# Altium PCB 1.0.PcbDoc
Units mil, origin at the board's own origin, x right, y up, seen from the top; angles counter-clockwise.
Board outline 1562.91 x 1190.73 mil, 2 copper layers (Top Layer, Bottom Layer); 62 components, 61 nets, 284 pads, 89 vias.
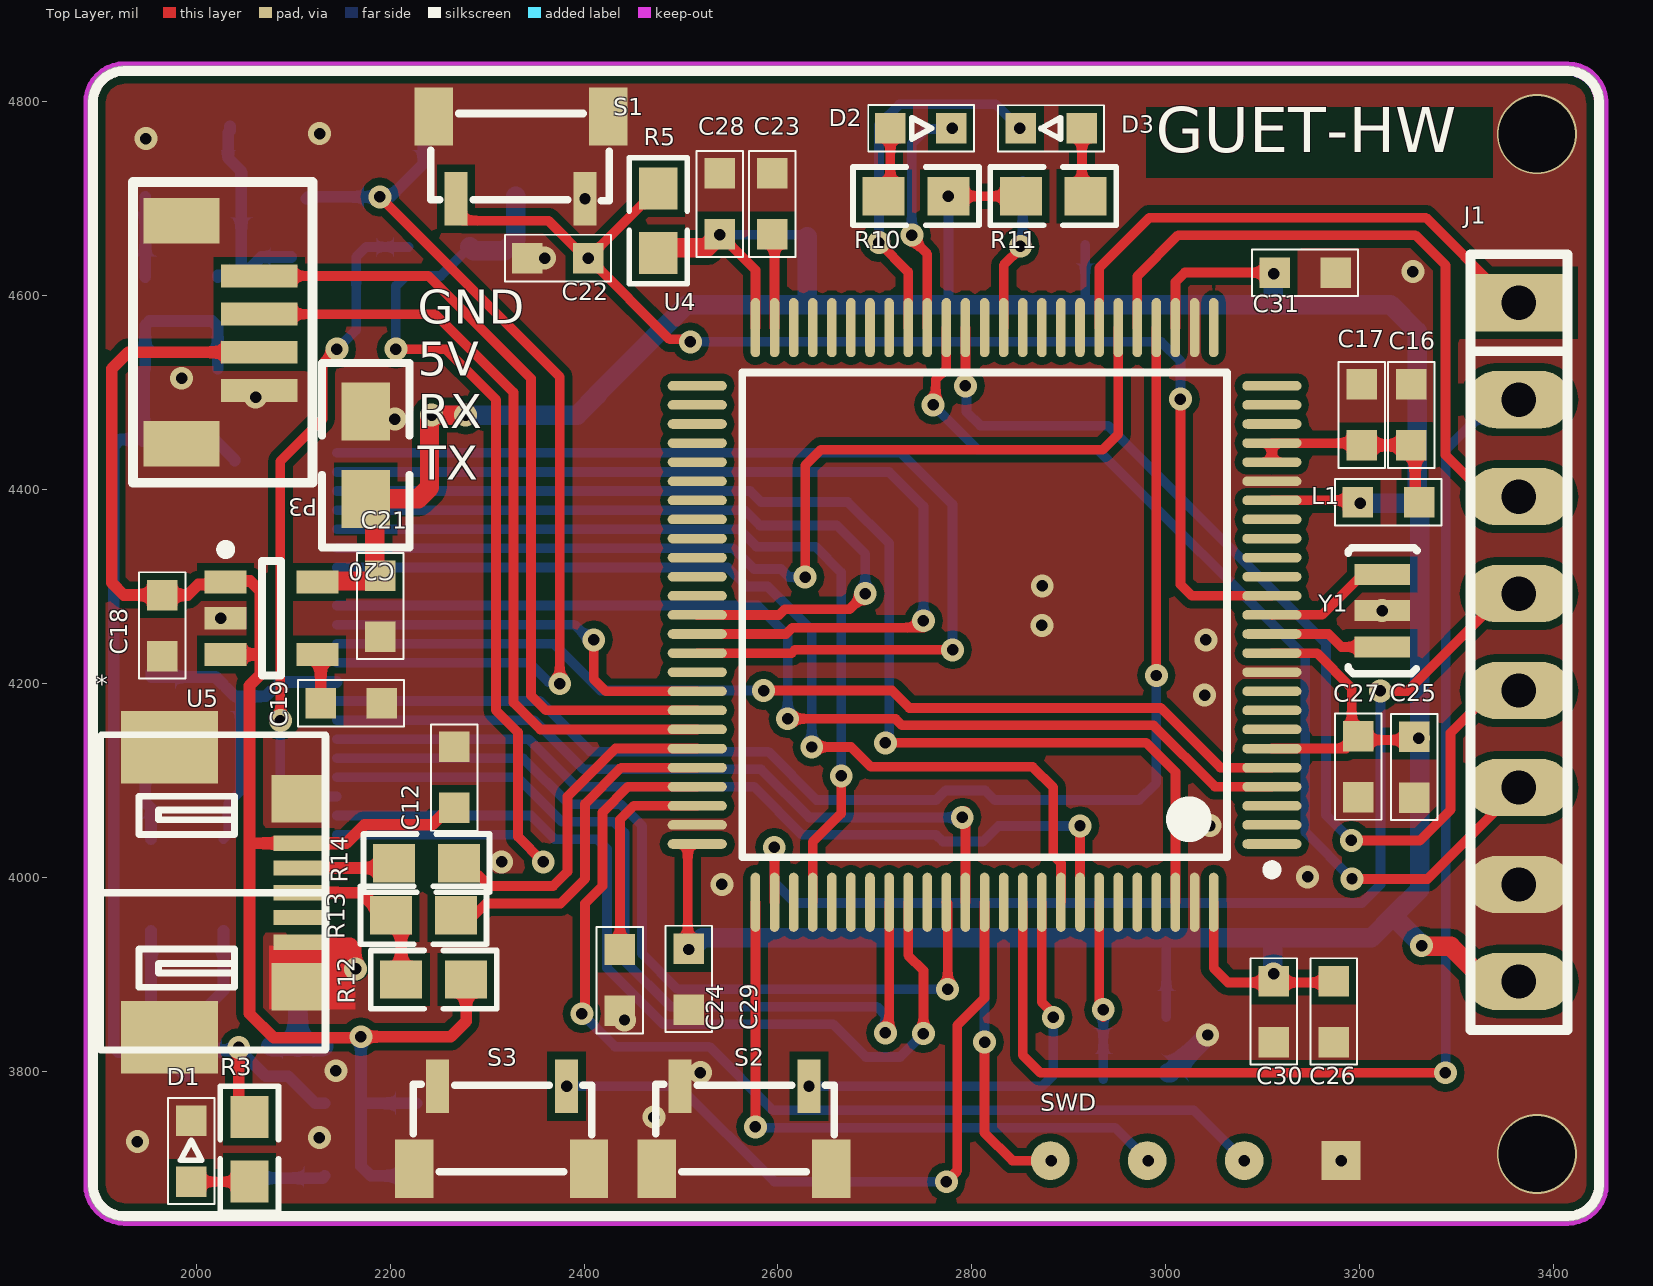
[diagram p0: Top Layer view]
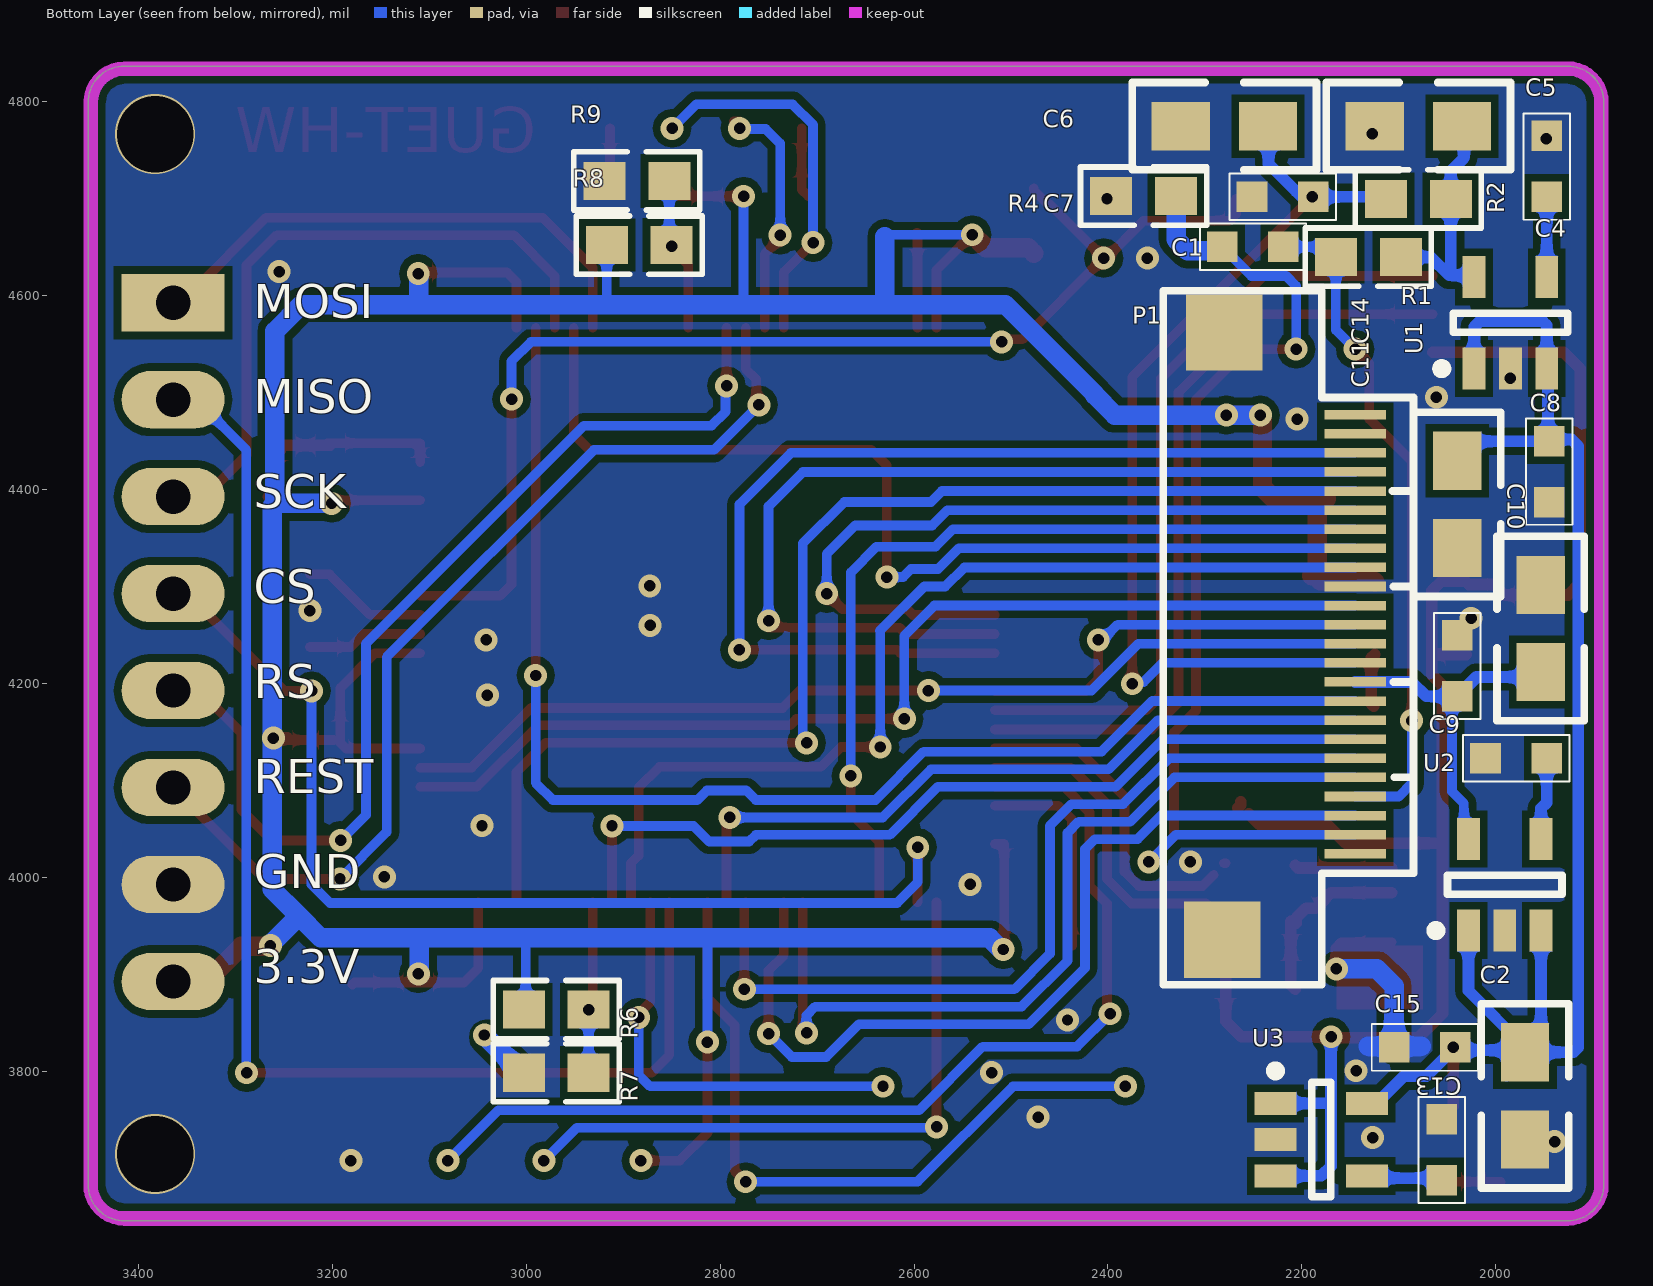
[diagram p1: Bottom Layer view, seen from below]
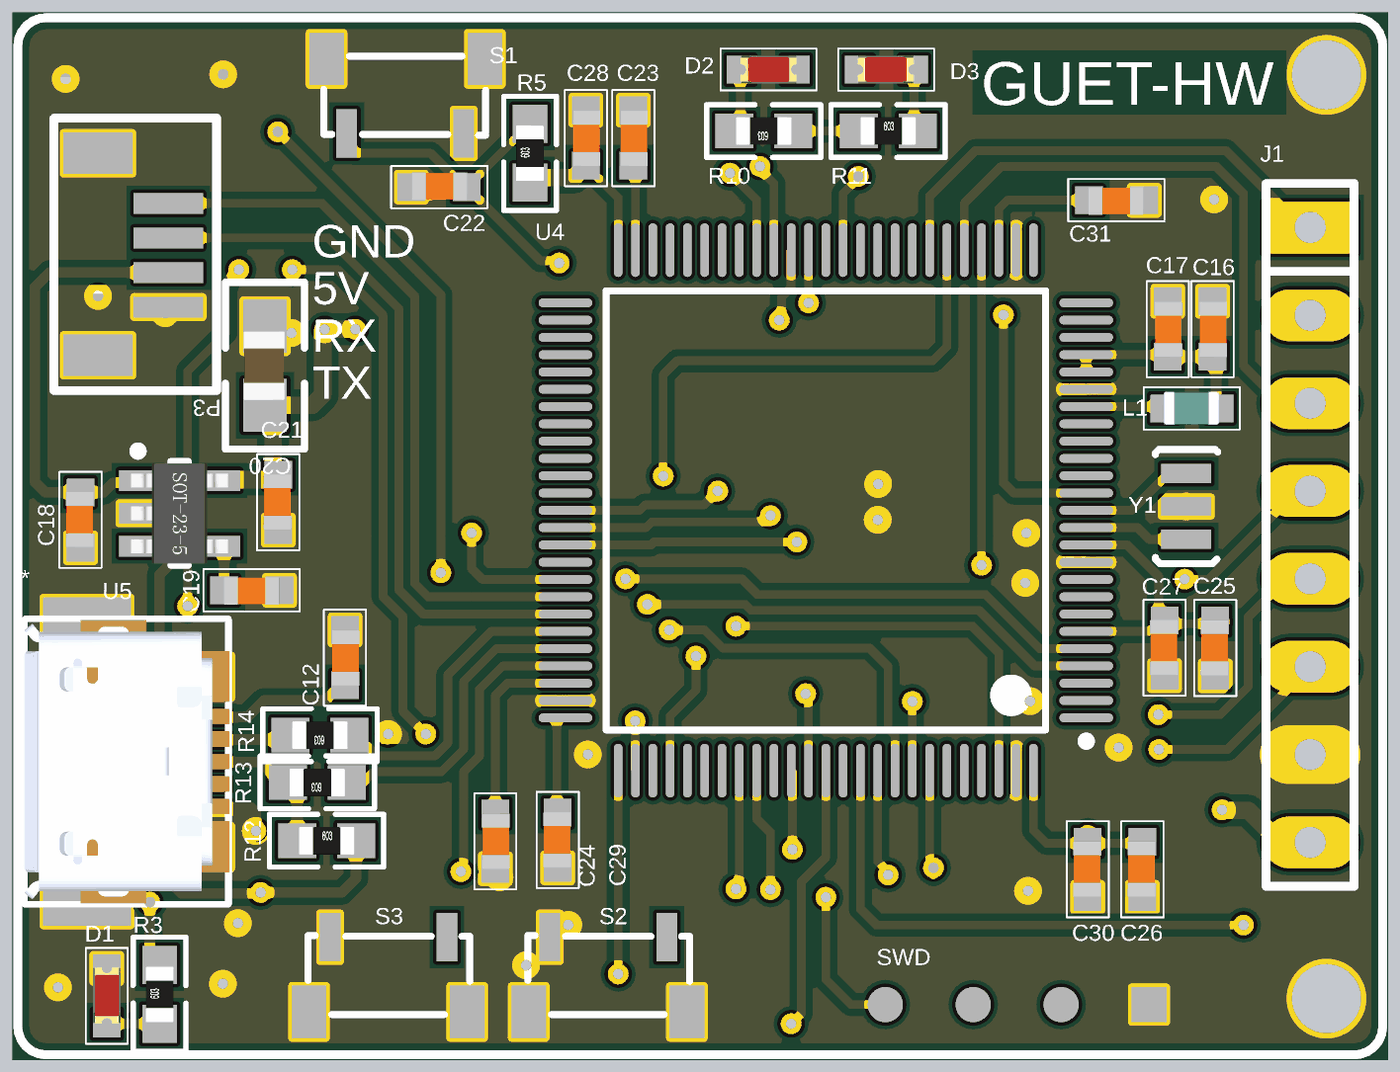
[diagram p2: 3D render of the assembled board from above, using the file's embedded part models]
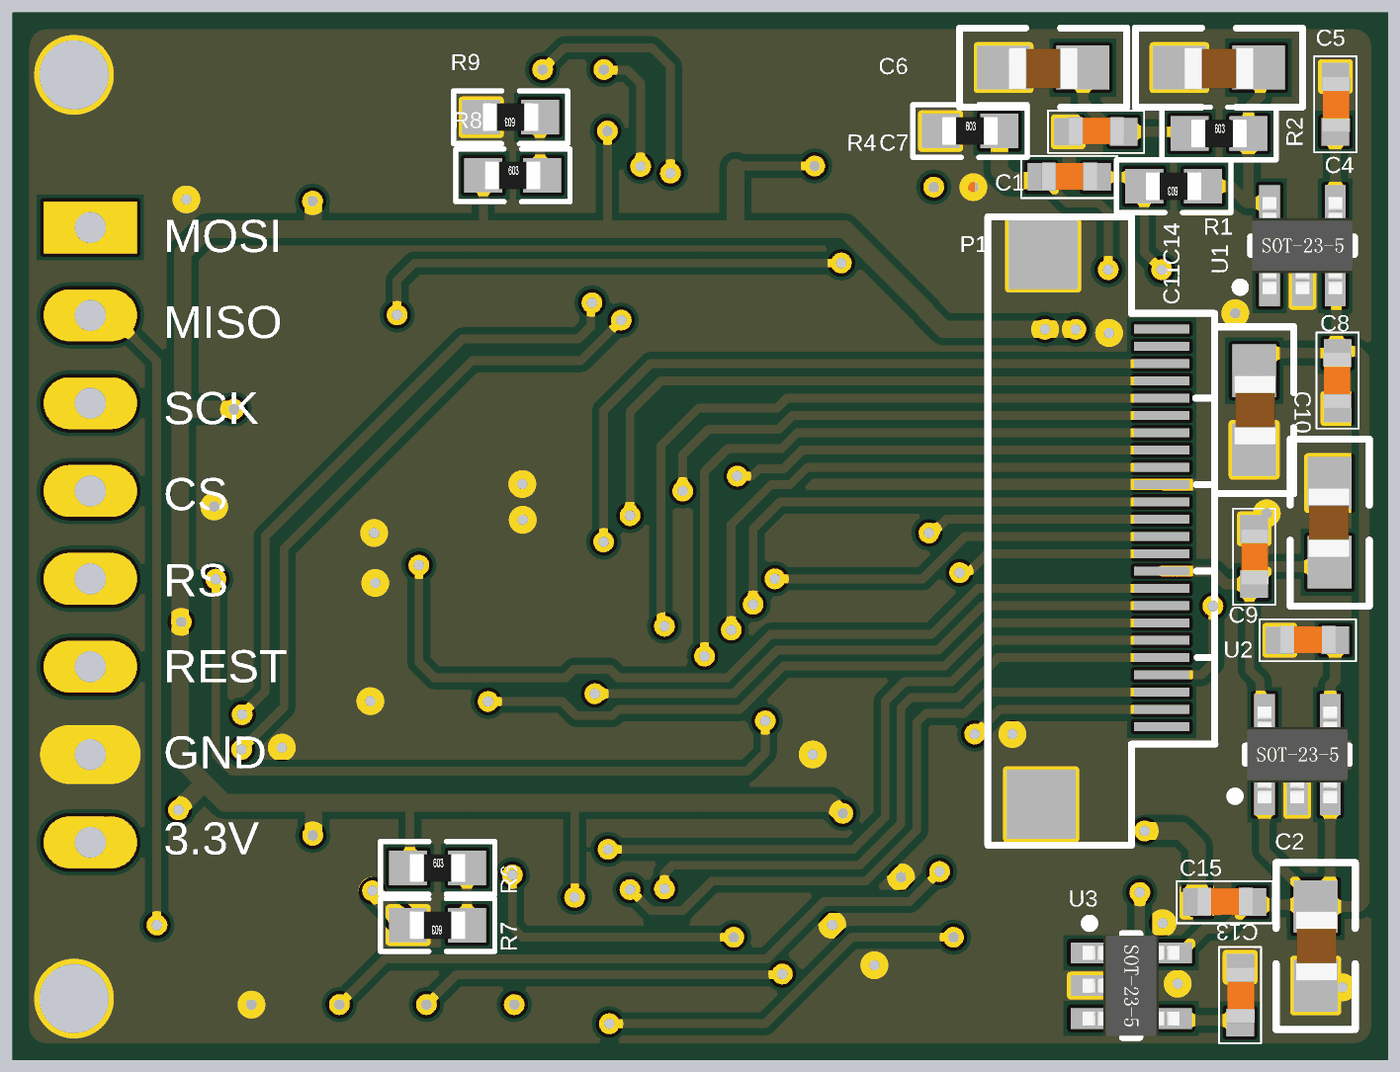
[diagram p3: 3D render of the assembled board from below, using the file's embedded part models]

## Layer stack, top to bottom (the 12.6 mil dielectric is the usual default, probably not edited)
Top Solder: solder mask 0.4, Solder Resist, Dk 3.5
Top Layer: signal copper 1.4
Dielectric 1: dielectric 12.6, FR-4, Dk 4.8
Bottom Layer: signal copper 1.4
Bottom Solder: solder mask 0.4, Solder Resist, Dk 3.5

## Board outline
1925.94,3646.14 cw(c1925.94,3683.41) 1888.68,3683.41 1888.68,4798.41 cw(c1893.69,4798.41) 1888.72,4799.01 cw(c1893.69,4799.6) 1888.68,4799.6 cw(c1925.94,4799.6) 1925.94,4836.87 cw(c1925.94,4831.85) 1926.53,4836.83 cw(c1927.11,4831.85) 1927.11,4836.87 3414.16,4836.87 cw(c3414.16,4831.85) 3414.28,4836.87 cw(c3414.41,4831.85) 3414.41,4836.87 cw(c3414.41,4799.69) 3451.59,4799.69 cw(c3446.57,4799.69) 3451.58,4799.55 cw(c3446.57,4799.41) 3451.59,4799.41 3451.59,3683.41 cw(c3414.32,3683.41) 3414.32,3646.14 1926.83,3646.14 cw(c1926.83,3651.16) 1926.38,3646.16 cw(c1925.94,3651.16)

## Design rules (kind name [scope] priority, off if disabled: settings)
Clearance [All] p1: gap=8 ignorepadtopadclearanceinfootprint=FALSE except(0: Arc-Hole Track-Hole SMDPad-Hole THPad-Hole Via-Hole Fill-Hole Poly-Hole Region-Hole Text-Hole; 10: Arc-Text Track-Text SMDPad-Text THPad-Text Via-Text Fill-Text Poly-Text Region-Text Text-Text)
PolygonConnect [All] p1: connectstyle=Direct reliefconductorwidth=10 reliefentries=4 polygonreliefangle="90 Angle" airgapwidth=10
RoutingVias [All] p1: holewidth=11.81 width=23.62 viastyle="Through Hole" minholewidth=4 minwidth=8 maxholewidth=19.68 maxwidth=39.37
SolderMaskExpansion [All] p1: expansion=4
Width [All] p1: maxlimit=50 minlimit=10 preferedwidth=10
30 further rules are at their usual default settings.

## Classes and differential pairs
component class ov7670电路（骑飞）: C1 C2 C4 C5 C6 C7 C8 C9 C10 C11 C12 C13 C14 C15 D1 P1 R1 R2 R3 R4 U1 U2 U3
component class F407VET6（主控）: * C16 C17 C18 C19 C20 C21 C22 C23 C24 C25 C26 C27 C28 C29 C30 C31 D2 D3 J1 L1 P3 R5 R6 R7 R8 R9 R10 R11 R12 R13 R14 S1 S2 S3 SWD U4 U5 Y1

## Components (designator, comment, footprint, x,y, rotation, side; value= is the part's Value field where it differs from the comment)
* "USB-Micro" USB-Micro 2055,3985 r270 top locked
C1 "CAP" C_0603 2250.56,4650.45 r180 bottom
C2 "10UF" C_0805 1970,3775 r90 bottom
C4 "10nF" C_0603 1947.6,4733.5 r270 bottom
C5 "10UF" C_0805 2080,4775 r180 bottom
C6 "4.7uF" C_0805 2280,4775 r180 bottom
C7 "4.7uF" C_0603 2220,4702.01 r180 bottom
C8 "1UF" C_0603 1945,4418.5 r90 bottom
C9 "10nF" C_0603 1979.25,4123.15 r180 bottom
C10 "10UF" C_0805 1954,4257 r270 bottom
C11 "0.1UF" C_0603 2040,4218.5 r270 bottom
C12 "1UF" C_0603 2265.99,4103.47 r270 top
C13 "10nF" C_0603 2056,3719.5 r270 bottom
C14 "10UF" C_0805 2040,4385 r90 bottom
C15 "0.1UF" C_0603 2073.5,3825 r180 bottom
C16 "CAP" C_0603 3253,4477.5 r270 top
C17 "CAP" C_0603 3202,4477.5 r270 top
C18 "1UF" C_0603 1965,4260 r90 top
C19 "10nF" C_0603 2160,4180 r180 top
C20 "10UF" C_0805 2174.94,4435.63 r270 top
C21 "0.1UF" C_0603 2190,4280 r90 top
C22 "CAP" C_0603 2373,4639 r0 top
C23 "CAP" C_0603 2594,4695 r270 top
C24 "CAP" C_0603 2437,3894.5 r270 top
C25 "CAP" C_0603 3256,4114 r90 top
C26 "CAP" C_0603 3173,3862 r90 top
C27 "CAP" C_0603 3198.34,4114.31 r90 top
C28 "CAP" C_0603 2540,4695 r270 top
C29 "CAP" C_0603 2508,3895.5 r90 top
C30 "CAP" C_0603 3111,3862 r90 top
C31 "CAP" C_0603 3143.71,4624 r180 top
D1 "LED" LED_0603 1995,3718.03 r90 top value=BLUE
D2 "LED" LED_0603 2747.37,4772.75 r0 top value=BLUE
D3 "LED" LED_0603 2881.89,4772.75 r180 top value=BLUE
J1 "CON8" sip-8 3364,4593 r270 top
L1 "L" L-0603 3229.5,4387 r180 top
P1 "FPC" FPC0.5-40P-A 2144.56,4409.78 r90 bottom locked
P3 "Header 4" HDR4*1_SH1.0 2135,4417.44 r90 top
R1 "Res1" 0603-1 2131.54,4640 r0 bottom value=10
R2 "Res1" 0603-1 2080,4700 r180 bottom value=10
R3 "Res1" 0603-1 2055,3720 r90 top value=1k
R4 "Res1" 0603-1 2363.24,4702.81 r180 bottom value=10
R5 "Res1" 0603-1 2476.55,4677.44 r90 top value=1K
R6 "Res1" 0603-1 2968.9,3864.01 r180 bottom
R7 "Res1" 0603-1 2968.9,3798.9 r0 bottom
R8 "Res1" 0603-1 2883.35,4652.39 r180 bottom
R9 "Res1" 0603-1 2885.83,4718.5 r0 bottom
R10 "Res1" 0603-1 2742.33,4702.75 r180 top value=1K
R11 "Res1" 0603-1 2883.86,4702.75 r0 top value=1K
R12 "Res1" 0603-1 2245,3895 r0 top
R13 "Res1" 0603-1 2234.43,3961.35 r180 top value=10
R14 "Res1" 0603-1 2237.55,4015 r180 top value=10
S1 "SW-PB" Switch-PB-C-M 2268,4700 r0 top locked
S2 "SW-PB" Switch-PB-C-M 2632,3785 r180 top locked
S3 "SW-PB" Switch-PB-C-M 2382,3785 r180 top locked
SWD "CON4" sip-4 3180.68,3708.32 r180 top locked
U1 "PAM3101" SOT23-5 1985,4572.24 r90 bottom
U2 "PAM3101" SOT23-5 1990.91,3992.76 r90 bottom
U3 "PAM3101" SOT23-5 2180,3730 r180 bottom
U4 "STM32F407VET6" STM-LQFP100_L 2813,4271 r180 top locked
U5 "PAM3101" SOT23-5 2077.76,4267.6 r0 top
Y1 "XTAL-3PIN" X-CPX20 3223,4275.4 r270 top

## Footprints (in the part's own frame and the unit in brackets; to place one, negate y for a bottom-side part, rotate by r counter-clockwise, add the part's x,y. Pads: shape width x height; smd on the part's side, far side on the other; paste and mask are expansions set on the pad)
0603-1 [mm] "0603带丝印"
  rect 1.1x1 smd: 1(-0.85,0) 2(0.85,0)
  silkscreen extent -1.65,-0.76 1.65,0.76, body extent -0.8,-0.4 0.8,0.4, height 0.3
C_0603 [mm]
  rect 0.8x0.8 smd: 1(-0.8,0) 2(0.8,0)
  silkscreen extent -1.38,-0.61 1.4,0.61, body extent -0.79,-0.38 0.81,0.42, height 0.5
C_0805 [mil]
  rect 60x50 smd: 1(-45,0) 2(45,0)
  silkscreen extent -95,-45 95,45, body extent -39,-25 39,23, height 37
FPC0.5-40P-A [mm] "FPC0.5mm接口"
  rect 0.25x1.6 smd: 1(-9.78,0.011) 2(-9.28,0.011) 3(-8.78,0.011) 4(-8.28,0.011) 5(-7.78,0.011) 6(-7.28,0.011) 7(-6.78,0.011) 8(-6.28,0.011) 9(-5.78,0.011) 10(-5.28,0.011) 11(-4.78,0.011) 12(-4.28,0.011) 13(-3.78,0.011) 14(-3.28,0.011) 15(-2.78,0.011) 16(-2.28,0.011) 17(-1.78,0.011) 18(-1.28,0.011) 19(-0.78,0.011) 20(-0.28,0.011) 21(0.22,0.011) 22(0.72,0.011) 23(1.22,0.011) 24(1.72,0.011)
  rect 2x2 smd: A(-12.029,3.5) B(3.871,3.44)
  silkscreen extent -13.21,-1.52 4.96,5.04
HDR4*1_SH1.0 [mm]
  rect 1.2x2 smd: 0(0.762,3.81) 0(6.604,3.81)
  rect 0.6x2 smd: 1(2.159,1.778) 2(3.159,1.778) 3(4.159,1.778) 4(5.159,1.778)
  silkscreen extent -0.25,0.38 7.62,5.08
L-0603 [mm]
  rect 0.8x0.8 smd: 1(-0.8,0) 2(0.8,0)
  silkscreen extent -1.38,-0.61 1.4,0.61, body extent -0.79,-0.48 0.81,0.47, height 0.78
LED_0603 [mm]
  rect 0.8x0.8 smd: 1(-0.8,0) 2(0.8,0)
  silkscreen extent -1.38,-0.6 1.39,0.61, body extent -0.8,-0.4 0.82,0.4, height 0.6
sip-4 [mil]
  rect 40x40 smd: 1(0,0)
  round 40 smd: 2(100,0) 3(200,0) 4(300,0)
sip-8 [mm]
  rect 1.5x2.7 hole 0.9: 1(0,0)
  oval 1.5x2.7 hole 0.9: 2(2.54,0) 3(5.08,0) 4(7.62,0) 5(10.16,0) 6(12.7,0) 7(15.24,0) 8(17.78,0)
  silkscreen extent -1.27,-1.27 19.05,1.27
SOT23-5 [mm] "Max4173"
  rect 1.1x0.6 smd: 1(-1.2,0.95) 2(-1.2,0) 3(-1.2,-0.95) 4(1.2,-0.95) 5(1.2,0.95)
  silkscreen extent -1.32,-1.5 0.25,1.93, body extent -1.4,-1.45 1.4,1.45, height 1.2
STM-LQFP100_L [mm] "Thin QFP, 100-Leads, Body 14x14mm, Pitch 0.5mm, IPC High Density"
  oval 1.55x0.25 smd: 1(-7.525,6) 2(-7.525,5.5) 3(-7.525,5) 4(-7.525,4.5) 5(-7.525,4) 6(-7.525,3.5) 7(-7.525,3) 8(-7.525,2.5) 9(-7.525,2) 10(-7.525,1.5) 11(-7.525,1) 12(-7.525,0.5) 13(-7.525,0) 14(-7.525,-0.5) 15(-7.525,-1) 16(-7.525,-1.5) 17(-7.525,-2) 18(-7.525,-2.5) 19(-7.525,-3) 20(-7.525,-3.5) 21(-7.525,-4) 22(-7.525,-4.5) 23(-7.525,-5) 24(-7.525,-5.5) 25(-7.525,-6) 51(7.525,-6) 52(7.525,-5.5) 53(7.525,-5) 54(7.525,-4.5) 55(7.525,-4) 56(7.525,-3.5) 57(7.525,-3) 58(7.525,-2.5) 59(7.525,-2) 60(7.525,-1.5) 61(7.525,-1) 62(7.525,-0.5) 63(7.525,0) 64(7.525,0.5) 65(7.525,1) 66(7.525,1.5) 67(7.525,2) 68(7.525,2.5) 69(7.525,3) 70(7.525,3.5) 71(7.525,4) 72(7.525,4.5) 73(7.525,5) 74(7.525,5.5) 75(7.525,6)
  oval 0.25x1.55 smd: 26(-6,-7.525) 27(-5.5,-7.525) 28(-5,-7.525) 29(-4.5,-7.525) 30(-4,-7.525) 31(-3.5,-7.525) 32(-3,-7.525) 33(-2.5,-7.525) 34(-2,-7.525) 35(-1.5,-7.525) 36(-1,-7.525) 37(-0.5,-7.525) 38(0,-7.525) 39(0.5,-7.525) 40(1,-7.525) 41(1.5,-7.525) 42(2,-7.525) 43(2.5,-7.525) 44(3,-7.525) 45(3.5,-7.525) 46(4,-7.525) 47(4.5,-7.525) 48(5,-7.525) 49(5.5,-7.525) 50(6,-7.525) 76(6,7.525) 77(5.5,7.525) 78(5,7.525) 79(4.5,7.525) 80(4,7.525) 81(3.5,7.525) 82(3,7.525) 83(2.5,7.525) 84(2,7.525) 85(1.5,7.525) 86(1,7.525) 87(0.5,7.525) 88(0,7.525) 89(-0.5,7.525) 90(-1,7.525) 91(-1.5,7.525) 92(-2,7.525) 93(-2.5,7.525) 94(-3,7.525) 95(-3.5,7.525) 96(-4,7.525) 97(-4.5,7.525) 98(-5,7.525) 99(-5.5,7.525) 100(-6,7.525)
  silkscreen extent -7.65,-6.35 6.35,6.8, body extent -7,-7 7,7, height 1.6
Switch-PB-C-M [mil]
  rect 39.37x60 smd: 0(-23,85) 0(157,85)
  rect 23.62x55.12 smd: 1(0,0) 2(133,0)
  silkscreen extent -26,-2 158,88
USB-Micro [mm]
  rect 1.9x2.54 smd: 0(-3.797,-2.096) 0(3.797,-2.095)
  rect 1.25x1.5 smd: 0(-2.451,1.333) 0(2.476,1.333)
  rect 0.4x1.4 smd: 1(-1.283,1.333) 2(-0.635,1.333) 3(0.013,1.333) 4(0.66,1.334) 5(1.308,1.334)
  silkscreen extent -4.13,-3.91 4.13,1.99, body extent -4.1,-3.91 4.1,2.02, height 2.77
X-CPX20 [mm] "贴片晶振"
  rect 0.55x1.45 smd: 1(-0.95,0) 2(0,0) 3(0.95,0)
  silkscreen extent -1.65,-0.89 1.65,0.91

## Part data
C2 C4 C5 C6 C7 C8 C9 C10 C11 C12 C13 C14 C15 C18 C19 C20 C21: library part CAP
J1 SWD: "Connector"
P1: library part FPC-40P, "FPC排线连接器"
P3: "接插件"
R1 R2 R3 R4 R5 R6 R7 R8 R9 R10 R11 R12 R13 R14: "贴片电阻"
S1 S2 S3: "Switch"
U1 U2 U3 U5: "LDO"
U4: "ARM Cortex-M4 32-bit MCU+FPU, 210 DMIPS, 512 kB Flash, 192 kB Internal RAM, 82 I/Os, 100-pin LQFP, -40 to 85 degC, Tray", I/Os (High Current)=82, Manufacturer=STMicroelectronics, Operating Frequency(F) (Processor speed) (MHz)=168, Supplier Part Number 1=497-12075-ND, Supply Voltage(Vcc) max (V)=3.6, Supply Voltage(Vcc) min (V)=1.8
Y1: "贴片晶振"

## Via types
v1: diameter 23.62, hole 11.81, Top Layer to Bottom Layer, 87 vias
v2: diameter 82.68, hole 78.74, Top Layer to Bottom Layer, 2 vias

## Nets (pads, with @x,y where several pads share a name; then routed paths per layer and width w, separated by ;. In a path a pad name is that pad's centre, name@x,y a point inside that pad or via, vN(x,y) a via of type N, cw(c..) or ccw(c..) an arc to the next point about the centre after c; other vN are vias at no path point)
1.8V: C10.2 C11.2 P1.10 U2.5 | length 369.1
  Bottom Layer w10: U2.5 2033.03,4044.72 2033.03,4076.65 2045.24,4088.87 C11.2@2045.24,4181.76 ; C11.2 C11.2@2045.24,4181.76 ; C11.2@2047.01,4180 C11.2@2045.24,4181.76
  Bottom Layer w12: C10.2 1954,4207 2020.01,4207 C11.2 2072.01,4187.01 2086.89,4201.89 P1.10
3.3V_MCU: C20.2 C21.2 C25.2 C26.2 C27.2 C28.2 C29.2 C30.2 C31.2 J1.8 L1.2 R5.1 R6.1 R8.1 R10.1 R11.1 SWD.4 U4.6 U4.11 U4.19 U4.28 U4.50 U4.75 U4.100 U5.5 | length 4847.9
  Top Layer w10: C29.2@2507,3929 2507,4034.7 2507.08,4034.78 U4.75 ; v1(2508,3926) C29.2 ; C28.2@2546.5,4657 2576.78,4626.72 U4.50 ; v1(2775.79,4702.75) R11.1 ; v1(2813,3830.5) 2813,3737 2841.68,3708.32 SWD.4 v1(2881.68,3708.32) ; U4.28 3009.85,4614.37 3019.48,4624 C31.2 ; U4.100 3049.22,3906.78 3064,3892 3177,3892 C26.2@3179,3890 ; U4.6 3185.71,4133.2 3191.61,4139.11 3191.61,4195.74 3155.72,4231.63 U4.11 ; U4.19 L1.2@3195.89,4389.11 ; C27.2@3198.5,4142 3252.01,4142 3255.5,4145.5 C25.2@3245.71,4145.5
  Top Layer w20: U5.5 2126,4306 2181,4306 C21.2@2186,4311 ; C20.2 2228.91,4390.63 2240.63,4402.35 2240.63,4475.38 v1@2243.05,4477.81 ; C20.2@2184.25,4379.21 2184.25,4317.24 C21.2 ; v1(2242.82,4477.07) v1(2277.82,4477.07) ; R5.1 2482.32,4649.74 2526.24,4649.74 C28.2 ; v1(3263.71,3930) 3264.4,3929.31 3293.5,3929.31 3329.81,3893 J1.8
  Bottom Layer w10: v1(2540,4663) 2628,4663 2630,4661 ; 2773.82,4591 2773.82,4596.45 2775.79,4598.42 v1(2775.79,4702.75) ; v1(2813,3830.5) 2813,3938 ; R8.1 2916.82,4591.51 2917.33,4591 ; R6.1@3000.39,3856.07 3000.39,3938
  Bottom Layer w20: v1(2242.82,4477.07) v1(2277.82,4477.07) 2392.97,4477.07 2413.56,4497.66 2413.56,4498.6 2505.95,4591 2630,4591 2773.82,4591 2917.33,4591 3106.75,4591 ; v1@2509,3926.02 2509.67,3926.69 2510.69,3926.69 2522,3938 2813,3938 3000.39,3938 3109,3938 ; 2630,4593 2630,4661 ; v1@3110,3900.94 3110,3937 3109,3938 ; v1(3111.21,4623) 3110.52,4622.3 3110.52,4594.77 3106.75,4591 ; v1(3200.5,4386) 3259,4386 ; v1(3263.71,3930) 3263.71,3930.98 3235.34,3959.34 3235.34,3961.66 ; 3106.75,4591 3231.5,4591 3259,4563.5 3259,4386 ; 3109,3938 3211.69,3938 3235.34,3961.66 ; 3235.34,3961.66 3261.81,3988.13 3261.81,4144 3261.81,4383.19 3259,4386
  other v1: 3111,3900.94 3260.5,4144
3V3: C2.2 C8.2 C14.2 C15.2 R3.2 U1.1 U1.3 U2.1 U2.3 U3.5 | length 1648.4
  Top Layer w12: v1(2044,3825) 2044,3764.46 R3.2
  Bottom Layer w12: U2.3 1953.5,3836.5 C2.2 ; U1.1 2022.4,4568.2 2016.6,4574 1952,4574 1947.6,4569.6 U1.3 1946.3,4523.7 1946.3,4451.3 C8.2 ; U2.1 2028.31,3883.31 1970,3825 C2.2 ; C14.2 2040,4431 2021,4450 C8.2 ; C15.2@2043.46,3823.55 2051.62,3815.39 2071.76,3795.25 2095.06,3795.25 2122.91,3767.4 U3.5 ; v1(2044,3825) 2046.2,3825 2047,3824.2 2044.91,3822.1 1989,3822.1 1989,3796 1970,3815 C2.2 ; C8.2 1943,4452 1922,4452 1915,4445 1915,3825 1920,3820 C2.2
5V: *.1 C12.2 C18.2 P3.2 R12.2 U3.1 U3.3 U5.1 U5.3 | length 1780.4
  Top Layer w12: C18.2@1963,4288 1959.5,4291.5 1925.5,4291.5 1913,4304 1913,4524.85 1929.96,4541.81 P3.2 ; C18.2 1991.5,4291.5 2002.4,4302.4 2027.91,4302.4 U5.1 2031.51,4306 2056,4306 2066.17,4295.83 2066.17,4209.17 2055,4198 2055,3860 2080,3835 v1@2171,3835 ; U5.3 2065,4230.2 ; 2057,4036 2057.5,4035.5 *.1 2154.75,4035.5 2173.71,4054.46 2243.46,4054.46 C12.2@2255,4066 ; 2152,4036 2154.5,4036 ; v1(2170,3836) 2262.43,3836 2278.46,3852.03 R12.2 ; C12.2@2262.99,4078.47 2262.99,4074.97 C12.2
  Bottom Layer w12: v1(2170,3836) 2170,3767.4 ; U3.3 2180,3692.6 2170,3702.6 2170,3767.4 ; U3.1 2170,3767.4
AGND: C1.1 P1.2 R4.2 | length 1103.1
  Top Layer w10: v1(2206,4545) 2257.24,4545 2309.23,4493.01 2309.23,4172.63 2331.86,4150 2331.86,4042.39 v1(2357.92,4016.33)
  Bottom Layer w10: P1.2 2329.84,4044.41 v1(2357.92,4016.33) ; v1(2206,4545) 2206,4610.37 2216.18,4620.55 2252.16,4620.55 C1.1
  Bottom Layer w20: C1.1 2286.07,4646.43 2318.06,4646.43 2329.77,4658.14 R4.2
AVDD(2.45~3.0V): C1.2 P1.4 R1.2 | length 697.8
  Top Layer w10: v1(2086.93,4162) 2086.93,4429.55 2130.46,4473.08 2130.46,4530.26 v1(2145.2,4545)
  Bottom Layer w10: v1@2086.93,4162.52 v1(2086.93,4162) 2086.93,4096.94 2100.09,4083.78 P1.4 ; v1(2145.2,4545) 2165,4564.8 R1.2 2175.45,4650.45 C1.2
BOOT0: R6.2 R7.1 U4.94 | length 184.1
  Top Layer w10: U4.94 2931.11,3864.08 2935.43,3859.76 v1@2935.43,3856.07
  Bottom Layer w10: R7.1@2935.43,3792.38 R6.2@2935.43,3856.06
  other v1: 2935.43,3864.01
BOOT1: R8.2 R9.1 U4.37 | length 159.4
  Top Layer w10: U4.37 2832.68,4631.68 2849.89,4648.88 v1(2849.89,4651.1) v1@2849.89,4652.39
  Bottom Layer w10: R8.2 2852.37,4654.87 R9.1
DCMI_D0: P1.24
DCMI_D1: P1.23
DCMI_D2: P1.19 U4.63 | length 787
  Top Layer w10: U4.63 2601,4271 2607,4277 2674,4277 v1(2690,4293)
  Bottom Layer w10: P1.19 2565.49,4379.06 2581.29,4363.25 2660.63,4363.25 2690,4333.88 v1(2690,4293)
DCMI_D3: P1.21 U4.64 | length 973.6
  Top Layer w10: U4.64 2608.31,4251.31 2614.85,4257.85 v1@2750,4257.85
  Bottom Layer w10: P1.21 2714.57,4418.43 2750,4383 v1(2750,4265)
DCMI_D4: P1.22 U4.65 | length 1071.7
  Top Layer w10: U4.65 2614.09,4231.63 2617.46,4235 v1(2780,4235)
  Bottom Layer w10: P1.22 2726.89,4438.11 2780,4385 v1(2780,4235)
DCMI_D5: P1.20 U4.98 | length 1245.1
  Top Layer w10: v1(2710.83,4139.11) 2979.79,4139.11 3009.85,4109.04 U4.98
  Bottom Layer w10: P1.20 2571.26,4398.74 2582.49,4387.51 2671.85,4387.51 2714.81,4344.55 2714.81,4143.09 v1(2710.83,4139.11)
DCMI_D6: P1.18 U4.79 | length 890.9
  Top Layer w10: U4.79 2635.83,4036.83 2665.19,4066.19 v1(2665.19,4105)
  Bottom Layer w10: P1.18 2559.72,4359.37 2577.72,4341.37 2638.63,4341.37 2665.19,4314.81 v1(2665.19,4105)
DCMI_D7: P1.16 U4.92 | length 1024.9
  Top Layer w10: v1(2634.81,4134.81) 2675.19,4134.81 2695.7,4114.3 2862.52,4114.3 2883.87,4092.95 2883.87,4022.87 2891.74,4015 U4.92
  Bottom Layer w10: P1.16 2548.18,4320 2567.87,4300.31 2589.45,4300.31 2635,4254.76 2634.81,4254.57 v1(2634.81,4134.81)
DCMI_D8: P1.14 U4.4 | length 1091.8
  Top Layer w10: v1(2610,4163.92) 2721.1,4163.92 2727.91,4157.11 2987.24,4157.11 3050.51,4093.83 U4.4
  Bottom Layer w10: P1.14 2579,4280.63 2610,4249.63 v1(2610,4163.92)
DCMI_D9: P1.12 U4.5 | length 1017.2
  Top Layer w10: v1(2585.17,4193) 2717.48,4193 2735.37,4175.11 2994.7,4175.11 3056.29,4113.52 U4.5
  Bottom Layer w10: P1.12 2368.83,4241.26 2399.81,4210.28 2399.81,4210.19 2417,4193 v1(2585.17,4193)
DCMI_HREF: P1.9 U4.29 | length 1372.2
  Top Layer w10: v1(2990.17,4208.54) U4.29
  Bottom Layer w10: P1.9 2354.41,4182.2 2406.62,4130 2590,4130 2639.81,4080.19 2763.13,4080.19 2772.94,4090 2813.69,4090 2823.5,4080.19 2972.43,4080.19 2990.17,4097.92 v1(2990.17,4208.54)
DCMI_PCLK: P1.17 U4.31 | length 1056.5
  Top Layer w10: v1(2628,4310) 2628,4425.17 2644.09,4441.26 2934.79,4441.26 2950.8,4457.26 U4.31
  Bottom Layer w10: P1.17 2553.95,4339.69 2575.33,4318.31 2603.09,4318.31 2611.4,4310 v1(2628,4310)
DCMI_VSYNC: P1.7 U4.93 | length 897.2
  Top Layer w10: U4.93 2911.43,4049.19 v1@2915.67,4053.43
  Bottom Layer w10: P1.7 2342.87,4142.84 2391.87,4093.83 2575.25,4093.83 2624.9,4044.19 2763.19,4044.19 2770,4037.38 2811.23,4037.38 2827.28,4053.43 v1(2911.43,4053.43)
DCMI_XCLK: P1.13 U4.67 | length 429.8
  Top Layer w10: v1(2410,4245.22) 2410,4205 2422.74,4192.26 U4.67
  Bottom Layer w10: P1.13 2390,4260.94 2410,4240.94 v1(2410,4245.22)
DOVDD(1.7~3.0V): C6.2 C7.2 P1.11 R2.1 | length 968.6
  Top Layer w10: v1(2189.48,4702.01) 2375,4516.49 v1(2375,4200)
  Bottom Layer w10: P1.11 2343.55,4221.57 2363.23,4201.89 ; C7.2 v1(2189.48,4702.01)
  Bottom Layer w12: R2.1 2115.46,4702 C7.2@2189,4702 ; C7.2@2201.19,4703 2234.5,4736.3 2234.5,4774.5 C6.2
GND: *.0 *.5 C2.1 C4.1 C5.1 C6.1 C7.1 C8.1 C9.1 C10.1 C11.1 C12.1 C13.1 C14.1 C15.1 C16.1 C17.1 C18.1 C19.1 C20.1 C21.1 C22.1 C23.1 C24.2 C25.1 C26.1 C27.1 C28.1 C29.1 C30.1 C31.1 D1.2 J1.7 P1.15 P1.A P1.B P3.0 P3.1 R4.1 R7.2 R9.2 S1.0 S1.2 S2.0 S2.2 S3.0 S3.2 SWD.1 U1.2 U2.2 U3.2 U4.10 U4.20 U4.27 U4.74 U4.99 U5.2 Y1.2 | length 321.6
  Top Layer w10: *.5 2159.54,3933.5 2165.46,3927.58 2165.46,3906.97 v1(2164.57,3906.08)
  Bottom Layer w20: 2076.8,3826.13 C15.1@2105,3826.13 ; C15.1 C15.1@2105,3826.13 ; 2131.92,3826.13 C15.1@2105,3826.13 ; v1(2164.57,3906.08) 2122.76,3906.08 2105,3888.32 C15.1@2105,3826.13 ; R7.2 3004.33,3798.9 3040.88,3835.45 v1@3040.88,3835.73
  other v1: 3180.68,3708.32 1939.42,3727.93 2127.05,3732.09 2471.99,3753.13 2520,3799.09 2144.1,3800.99 3043.04,3837.83 2441.75,3853.32 2542.21,3993.06 3146.14,4000.94 2315,4016.33 3045.44,4053.75 3039.85,4188.36 3041.14,4245.22 2872.06,4260.22 2025.64,4267.59 3223,4275.4 2872.52,4300.95 2205,4472.89 2061.46,4495.42 1985,4515 3254.75,4625 2359.42,4639 2401,4700 1948.21,4762.17 2127.38,4767.33
  other v2: 3382.56,3715.14 3382.56,4766.74
KEY1: S2.1 U4.91 | length 439.6
  Top Layer w10: U4.91 2872.06,3871.5 2883.87,3859.69 v1(2883.87,3856)
  Bottom Layer w10: v1(2632,3785) 2872.06,3785 2883.87,3796.81 v1(2883.87,3856)
KEY2: S3.1 U4.88 | length 736.9
  Top Layer w10: v1(2773.55,3686.54) 2785,3697.98 2785,3848.04 2813,3876.04 U4.88
  Bottom Layer w10: v1(2382,3785) 2497.9,3785 2596.37,3686.54 v1(2773.55,3686.54)
LED1: D2.2 U4.41 | length 251.6
  Top Layer w10: v1(2738,4662.54) 2738,4658.85 2753.94,4642.9 U4.41 ; D2.2 D2.2@2779.76,4772.75 ; D2.2@2779.86,4779.75 D2.2@2785.86,4779.75
  Bottom Layer w10: v1(2738,4662.54) 2738,4757.19 2752.95,4772.14 2779.15,4772.14 v1(2779.76,4772.75)
LED2: D3.2 U4.42 | length 387.1
  Top Layer w10: v1(2704.06,4654.87) 2734.26,4624.67 U4.42 ; v1(2849.5,4772.74) D3.2
  Bottom Layer w10: v1(2704.06,4654.87) 2704.06,4776.58 2725.05,4797.56 2824.68,4797.56 v1(2849.5,4772.74)
NC: P1.1
Net*_2: *.2 R14.2 | length 100.7
  Top Layer w12: *.2 2204,4010 R14.2@2207,4013
Net*_3: *.3 R12.1 R13.2 | length 186.7
  Top Layer w12: *.3 2170.06,3984.5 2185.87,3968.69 2195.88,3968.69 2206,3958.57 R13.2@2206,3953 ; R12.1@2207,3885 2211.54,3889.54 R12.1 R13.2@2211.54,3955
NetC4_2: C4.2 U1.4 | length 82.5
  Bottom Layer w12: U1.4 C4.2
NetC5_2: C5.2 R1.1 R2.2 U1.5 | length 246.1
  Bottom Layer w12: U1.5 2022.4,4621.08 2048.09,4621.08 ; C5.2 2035,4770.43 2033.03,4768.46 2033.03,4742.03 2046.54,4728.52 R2.2 2046.54,4622.63 2048.09,4621.08 ; R1.1 2067.01,4640 2048.09,4621.08
NetC9_2: C9.2 U2.4 | length 85.5
  Bottom Layer w12: C9.2 1947.75,4077.25 1953.5,4071.5 U2.4
NetC13_2: C13.2 U3.4 | length 78.7
  Bottom Layer w12: C13.2 2058.3,3690.3 2130.46,3690.3 U3.4
NetC19_2: C19.2 U5.4 | length 55.7
  Top Layer w12: U5.4 2128.5,4226.69 C19.2 2128.5,4179.5 C19.2@2126,4177
NetC23_2: C23.2 U4.49 | length 98.8
  Top Layer w10: C23.2@2595,4663 C23.2@2597,4665 ; C23.2@2596,4663 2596.46,4662.54 U4.49
NetC24_1: C24.1 U4.73 | length 216.1
  Top Layer w10: C24.1@2437,3930 2437,4060 2451.15,4074.15 U4.73 ; C24.1@2440,3928.5 C24.1@2440,3929
NetD1_1: D1.1 R3.1 | length 60
  Top Layer w10: D1.1 R3.1
NetD2_1: D2.1 R10.2 | length 72.9
  Top Layer w10: R10.2 2715.87,4709.76 D2.1
NetD3_1: D3.1 R11.2 | length 64.2
  Top Layer w10: D3.1 2913.39,4709.22 R11.2@2913.86,4708.75
NRST: C22.2 R5.2 S1.1 U4.14 | length 1257.1
  Top Layer w10: S1.1 2268,4684.25 2274.81,4677.44 2363.41,4677.44 C22.2@2403.17,4637.68 ; R5.2 2476.55,4708.94 2461.87,4694.25 2459.75,4694.25 v1(2404.5,4639) 2488.33,4555.17 2507.07,4555.17 v1(2509.67,4552.56) ; v1(3014.98,4493.5) 3014.98,4302.4 3026.69,4290.69 U4.14
  Bottom Layer w10: v1(2509.67,4552.56) 2995.09,4552.56 3014.98,4532.67 v1(3014.98,4493.5)
OS_8M_IN: U4.12 Y1.3 | length 119.3
  Top Layer w10: U4.12 3167.69,4251.31 3181,4238 Y1.3
OS_8M_OUT: U4.13 Y1.1 | length 131.1
  Top Layer w10: U4.13 3109.34,4271.08 3160.92,4271.08 3202.65,4312.8 Y1.1
PWDN: P1.8 U4.87 | length 788.3
  Top Layer w10: v1(2790,4062.19) 2790,4065.34 2793.31,4068.65 U4.87
  Bottom Layer w10: P1.8 2348.64,4162.52 2399.33,4111.83 2582.71,4111.83 2632.36,4062.19 v1(2790,4062.19)
RESET: P1.6 U4.86 | length 896.3
  Top Layer w10: U4.86 2775,3973.37 v1(2775,3885)
  Bottom Layer w10: P1.6 2337.1,4123.15 2384.42,4075.83 2437.66,4075.83 2459.75,4053.75 2459.75,3921.75 2496.5,3885 v1(2775,3885)
SIOC: P1.5 U4.83 | length 899.1
  Top Layer w10: v1(2710.83,3840) 2714.57,3843.75 U4.83
  Bottom Layer w10: P1.5 2331.33,4103.47 2376.96,4057.83 2430.21,4057.83 2441.75,4046.29 2441.75,3914.29 2489.04,3867 2701.86,3867 2710.83,3858.04 v1(2710.83,3840)
SIOD: P1.3 U4.84 | length 932
  Top Layer w10: U4.84 2734.26,3920 2750,3904.26 v1(2750,3839.21)
  Bottom Layer w10: P1.3 2345.24,4064.09 2369.5,4039.83 2413.47,4039.83 2423.75,4029.55 2423.75,3906.84 2481.59,3849 2656.74,3849 2690.55,3815.19 2725.98,3815.19 v1(2750,3839.21)
SPI1_CS: J1.4 U4.77 | length 1118.4
  Top Layer w10: v1(2596.16,4031.3) 2596.39,4031.08 2596.39,3974.82 U4.77 ; v1(3221.24,4192.61) 3249.04,4192.61 3349.43,4293 J1.4
  Bottom Layer w10: v1(2596.16,4031.3) 2596.16,3995.22 2617.39,3973.99 3202.17,3973.99 3221.24,3993.06 v1(3221.24,4192.61)
SPI1_MISO: J1.2 U4.90 | length 1340.3
  Top Layer w10: U4.90 2852.37,3817.13 2870.6,3798.9 v1(3288.19,3798.9)
  Bottom Layer w10: v1(3288.19,3798.9) 3288.52,3799.23 3288.52,4441.14 3340.38,4493 J1.2
SPI1_MOSI: J1.1 U4.32 | length 552.1
  Top Layer w10: U4.32 2931.11,4628.77 2982.88,4680.54 3267.98,4680.54 3346.13,4602.39 3354.61,4602.39 J1.1
SPI1_REST: J1.6 U4.40 | length 1036.5
  Top Layer w10: v1(2760,4487.54) 2762.61,4490.14 2762.61,4513.83 2773.55,4524.77 2773.55,4567.18 U4.40 ; v1(3191.89,3998.81) 3269.81,3998.81 J1.6
  Bottom Layer w10: v1(2760,4487.54) 2806.28,4441.26 2929.89,4441.26 3143.71,4227.44 3143.71,4046.99 v1(3191.89,3998.81)
SPI1_RS: J1.5 U4.39 | length 1053.9
  Top Layer w10: v1(2793.31,4507.22) U4.39 ; v1(3191.29,4038.48) 3261.86,4038.48 3293.35,4069.98 3293.35,4149.16 3337.19,4193 J1.5
  Bottom Layer w10: v1(2793.31,4507.22) 2794.38,4506.15 2794.38,4480.41 2808.6,4466.19 2940.28,4466.19 3165.04,4241.42 3165.04,4064.72 v1(3191.29,4038.48)
SPI1_SCK: J1.3 U4.30 | length 690.4
  Top Layer w10: U4.30 2970.48,4620.32 3012.7,4662.54 3257.21,4662.54 3288.19,4631.56 3288.19,4435.85 3331.04,4393 J1.3
SWCLK: SWD.3 U4.76 | length 657.6
  Top Layer w10: v1(2576.78,3743.15) U4.76 ; SWD.3@2976.69,3712.31 SWD.3 v1(2981.68,3708.32)
  Bottom Layer w10: v1(2576.78,3743.15) 2577.74,3742.19 2947.81,3742.19 v1(2981.68,3708.32)
SWDIO: SWD.2 U4.72 | length 1070.7
  Top Layer w10: v1(2397.81,3859.76) 2401,3862.95 2401,3973.41 2419,3991.41 2419,4067.46 2445.38,4093.83 U4.72
  Bottom Layer w10: v1(2397.81,3859.76) 2431.83,3825.74 2529.27,3825.74 2594.82,3760.19 3028.81,3760.19 v1(3080.68,3708.32)
USART1-RX: P3.4 U4.68 | length 828.7
  Top Layer w10: P3.4 2239.45,4620.55 2345.23,4514.77 2345.23,4188 2360.66,4172.57 U4.68
USART1-TX: P3.3 U4.69 | length 816.5
  Top Layer w10: P3.3 2246.51,4581.18 2327.23,4500.46 2327.23,4180.55 2354.89,4152.89 U4.69
USB_D+: R13.1 U4.71 | length 349.3
  Top Layer w10: R13.1@2278.46,3955 2280.43,3955 2298.95,3973.52 2375.65,3973.52 2401,3998.87 2401,4076.24 2438.28,4113.52 U4.71
USB_D-: R14.1 U4.70 | length 336.5
  Top Layer w10: R14.1@2278.46,4015 R14.1@2280.43,4015 ; R14.1@2291,4003 2302.48,3991.52 2368.2,3991.52 2383,4006.32 2383,4083.69 2432.51,4133.2 U4.70
VDDA: C16.2 C17.2 L1.1 U4.21 U4.22 | length 250.9
  Top Layer w10: U4.21 U4.22 3204.83,4448.17 C17.2@3206.99,4446.01 ; L1.1 L1.1@3267,4393 ; L1.1@3265.5,4395 L1.1@3265.98,4394.52
  Top Layer w12: C17.2 3206.99,4446.01 3252.01,4446.01 C16.2@3253,4447 ; C16.2@3253,4441.5 C16.2@3254.75,4439.75 ; C16.2 3257,4442.01 3257,4388 L1.1@3264,4381
pads on no net: *.4 U4.1 U4.2 U4.3 U4.7 U4.8 U4.9 U4.15 U4.16 U4.17 U4.18 U4.23 U4.24 U4.25 U4.26 U4.33 U4.34 U4.35 U4.36 U4.38 U4.43 U4.44 U4.45 U4.46 U4.47 U4.48 U4.51 U4.52 U4.53 U4.54 U4.55 U4.56 U4.57 U4.58 U4.59 U4.60 U4.61 U4.62 U4.66 U4.78 U4.80 U4.81 U4.82 U4.85 U4.89 U4.95 U4.96 U4.97

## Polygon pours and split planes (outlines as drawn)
GND on Top Layer "Top Layer-GND" (solid, pour order 26): 1926.53,4836.83 1925.91,4836.83 1888.68,4799.6 1888.68,3671.57 1914.11,3646.14 3424.99,3646.14 3451.59,3672.74 3451.2,3673.13 3451.2,4801.33 3415.67,4836.87
no net on Top Layer "Top Layer-No Net 3" (solid, pour order 2): 1892.34,3694.17
no net on Top Layer "Top Layer-No Net 4" (solid, pour order 0): 1895.63,3651.25
GND on Bottom Layer "Bottom Layer-GND" (solid, pour order 24): 1925.94,4836.87 1888.68,4799.6 1888.68,3671.57 1914.11,3646.14 3424.99,3646.14 3451.59,3672.74 3451.59,4800.95 3415.67,4836.87

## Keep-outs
Keep-Out Layer:
  lines w10: 1893.69,3683.41 ccw(c1925.94,3683.41) 1925.94,3651.16 ; 1893.69,3684.79 1893.69,4797.93 ; 1893.69,4799.6 cw(c1925.94,4799.6) 1925.94,4831.85 ; 1927.04,3651.16 3414.32,3651.16 ccw(c3414.32,3683.41) 3446.57,3683.41 3446.57,4799.41 ; 1927.11,4831.85 3414.16,4831.85 ; 3078.01,3646.14 3414.32,3646.14 ccw(c3414.32,3683.41) 3451.59,3683.41 3451.59,4799.41 ccw(c3446.57,4799.41) 3451.2,4801.33 ccw(c3413.98,4799.6) 3414.25,4836.87 ; 3096.72,3646.14 1927.04,3646.14 cw(c1927.04,3651.16) 1926.49,3646.17 ; 3413.98,4831.85 cw(c3413.98,4799.6) 3446.23,4799.6 ; 3446.57,4672.43 3446.57,4765 ; 1888.75,4798.77 cw(c1893.69,4799.6) 1888.68,4799.6 cw(c1925.94,4799.6) 1925.94,4836.87 cw(c1925.94,4831.85) 1926.53,4836.83 ; 1888.75,4798.77 ccw(c1893.69,4797.93) 1888.68,4797.93 1888.68,3684.79 ccw(c1893.69,3684.79) 1888.73,3684.1 ccw(c1893.69,3683.41) 1888.68,3683.41 ccw(c1925.94,3683.41) 1925.94,3646.14 ccw(c1925.94,3651.16) 1926.49,3646.17 ; 1888.75,4798.77 1888.75,4798.77 ; 1926.49,3646.17 1926.49,3646.17 ; 1926.53,4836.83 cw(c1927.11,4831.85) 1927.11,4836.87 3414.16,4836.87 cw(c3414.16,4831.85) 3414.25,4836.87 ; 1926.53,4836.83 1926.53,4836.83 ; 3414.25,4836.87 3414.25,4836.87

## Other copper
Top Layer:
  rectangle net GND: 2075,3864.01 2164.57,3930
  text "GUET-HW" at 2989.67,4732.56 h80

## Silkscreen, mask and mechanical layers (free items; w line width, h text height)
Top Overlay:
  lines w10: 1893.69,4798.41 1893.69,3683.41 ccw(c1925.94,3683.41) 1925.94,3651.16 ; 1893.69,4799.6 cw(c1925.94,4799.6) 1925.94,4831.85 ; 1926.83,3651.16 3414.32,3651.16 ccw(c3414.32,3683.41) 3446.57,3683.41 3446.57,4799.41 ; 1927.11,4831.85 3414.16,4831.85 ; 3414.41,4831.85 cw(c3414.41,4799.69) 3446.57,4799.69
  text "GUET-HW" at 2989.67,4732.56 h80
  text "GND" at 2228.63,4559.12 h60
  text "5V" at 2228.63,4505.74 h60
  text "RX" at 2228.63,4451.69 h60
  text "TX" at 2228.63,4398.31 h60
Bottom Overlay:
  text "MOSI" at 3280.86,4565.15 h60
  text "MISO" at 3280.86,4467.18 h60
  text "SCK" at 3280.86,4369.22 h60
  text "CS" at 3280.86,4271.26 h60
  text "RS" at 3280.86,4173.29 h60
  text "REST" at 3280.86,4075.33 h60
  text "GND" at 3280.86,3977.37 h60
  text "3.3V" at 3280.86,3879.4 h60
Mechanical 1:
  lines w10: 2018.98,3646.14 1927.04,3646.14 cw(c1927.04,3651.16) 1926.49,3646.17 ; 3078.01,3646.14 3414.32,3646.14 ccw(c3414.32,3683.41) 3451.59,3683.41 3451.59,4799.41 ccw(c3446.57,4799.41) 3451.2,4801.33 ccw(c3413.98,4799.6) 3414.25,4836.87 ; 1888.75,4798.77 cw(c1893.69,4799.6) 1888.68,4799.6 cw(c1925.94,4799.6) 1925.94,4836.87 cw(c1925.94,4831.85) 1926.53,4836.83 ; 1888.75,4798.77 ccw(c1893.69,4797.93) 1888.68,4797.93 1888.68,3684.79 ccw(c1893.69,3684.79) 1888.73,3684.1 ccw(c1893.69,3683.41) 1888.68,3683.41 ccw(c1925.94,3683.41) 1925.94,3646.14 ccw(c1925.94,3651.16) 1926.49,3646.17 ; 1888.75,4798.77 1888.75,4798.77 ; 1926.49,3646.17 1926.49,3646.17 ; 1926.53,4836.83 cw(c1927.11,4831.85) 1927.11,4836.87 3414.16,4836.87 cw(c3414.16,4831.85) 3414.25,4836.87 ; 1926.53,4836.83 1926.53,4836.83 ; 3414.25,4836.87 3414.25,4836.87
